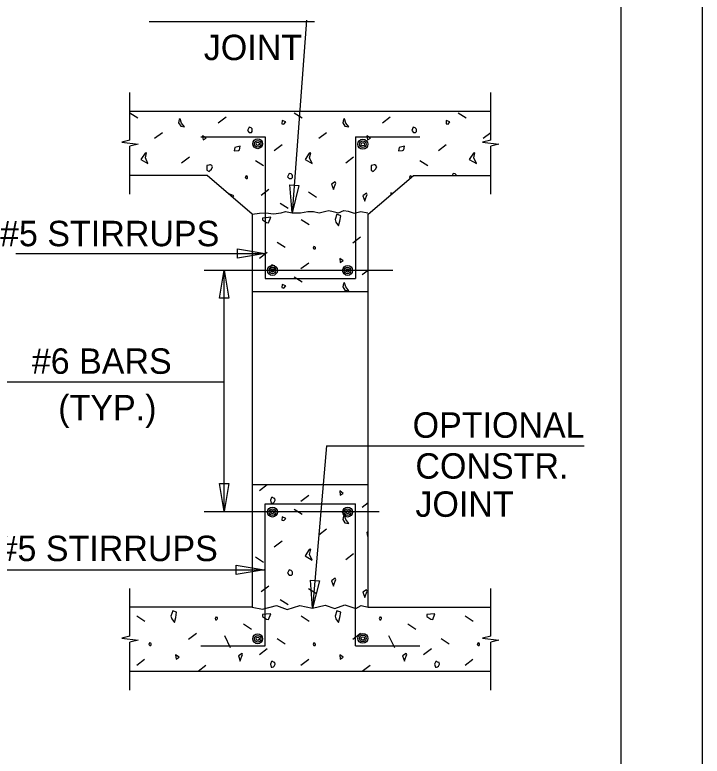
# Model space of a CAD drawing. Extents: x 0 to 34, y 0 to 23.5.
# Drawn here: x 29.778 to 34, y 4.606 to 9.162 of the extents above; entities that cross this region are included whole.
import ezdxf

# ---------------------------------------------------------------- set-up
doc = ezdxf.new("R2010")
doc.units = 0
for name, color, linetype in [('BORDER_ANNO_Cutsheet', 7, 'Continuous'), ('BRDG_ANNO_Anno-Sheet', 7, 'Continuous'), ('BRDG_ANNO_General-Notes', 7, 'Continuous'), ('BRDG_BASE_Dtlctrln', 7, 'Continuous'), ('BRDG_BASE_Obj-Line', 7, 'Continuous'), ('BRDG_BASE_Pattern', 7, 'Continuous'), ('BRDG_BASE_Rebar', 7, 'Continuous')]:
    doc.layers.add(name, color=color, linetype=linetype)

msp = doc.modelspace()

# ---------------------------------------------------------------- linework, layer by layer
at = {"layer": 'BORDER_ANNO_Cutsheet'}
msp.add_lwpolyline([(0, 22), (34, 22), (34, 0), (0, 0)], close=True, dxfattribs=at)
at = {"layer": 'BRDG_ANNO_Anno-Sheet'}
msp.add_lwpolyline([(1.5, 21.5), (33.5, 21.5), (33.5, 0.5), (1.5, 0.5)], close=True, dxfattribs=at)
at = {"layer": 'BRDG_ANNO_General-Notes'}
for p, q in [((30.6025, 9.1206), (31.618, 9.1206)), ((31.5703, 9.1292), (31.4824, 7.9448)), ((31.4667, 8.1175), (31.5235, 8.1133)), ((31.4824, 7.9448), (31.4667, 8.1175)), ((31.5235, 8.1133), (31.4824, 7.9448)), ((31.1453, 7.6665), (31.1453, 7.7235)), ((31.1453, 7.7235), (31.3163, 7.695)), ((29.7843, 7.695), (31.3163, 7.695)), ((31.3163, 7.695), (31.1453, 7.6665)), ((31.0365, 7.4209), (31.0649, 7.5919)), ((31.0649, 6.1102), (31.0649, 7.5919)), ((31.0649, 7.5919), (31.0934, 7.4209)), ((31.0934, 7.4209), (31.0365, 7.4209)), ((29.3401, 6.9065), (31.0649, 6.9065)), ((31.693, 6.5123), (31.6071, 5.5158)), ((31.693, 6.5123), (33.2743, 6.5123)), ((31.0365, 6.2812), (31.0934, 6.2812)), ((31.0649, 6.1102), (31.0365, 6.2812)), ((31.0934, 6.2812), (31.0649, 6.1102)), ((29.728, 5.752), (31.3093, 5.752)), ((31.1383, 5.7235), (31.1383, 5.7805)), ((31.1383, 5.7805), (31.3093, 5.752)), ((31.3093, 5.752), (31.1383, 5.7235)), ((31.5934, 5.6886), (31.6502, 5.6837)), ((31.6071, 5.5158), (31.5934, 5.6886)), ((31.6502, 5.6837), (31.6071, 5.5158))]:
    msp.add_line(p, q, dxfattribs=at)
at = {"layer": 'BRDG_BASE_Dtlctrln'}
for p, q in [((30.9419, 7.5919), (32.1005, 7.5919)), ((30.9419, 6.1102), (32.0158, 6.1102))]:
    msp.add_line(p, q, dxfattribs=at)
at = {"layer": 'BRDG_BASE_Obj-Line'}
for p, q in [((30.485, 8.3912), (30.485, 8.685)), ((32.7017, 8.3912), (32.7017, 8.685)), ((30.485, 8.5704), (32.7017, 8.5704)), ((30.485, 8.3912), (30.435, 8.3788)), ((32.7017, 8.3912), (32.6517, 8.3788)), ((30.435, 8.3788), (30.535, 8.3662)), ((30.535, 8.3662), (30.485, 8.3537)), ((30.485, 8.06), (30.485, 8.3537)), ((32.6517, 8.3788), (32.7517, 8.3662)), ((32.7517, 8.3662), (32.7017, 8.3537)), ((32.7017, 8.06), (32.7017, 8.3537)), ((30.96, 8.1746), (30.485, 8.1746)), ((31.2371, 7.9371), (30.96, 8.1746)), ((31.9496, 7.9371), (32.2267, 8.1746)), ((32.2267, 8.1746), (32.7017, 8.1746)), ((31.2371, 7.9371), (31.2371, 5.5225)), ((31.9496, 5.5225), (31.9496, 7.9371)), ((31.2371, 7.4621), (31.9496, 7.4621)), ((31.2371, 6.2746), (31.9496, 6.2746)), ((30.485, 5.3433), (30.485, 5.6371)), ((32.7017, 5.3433), (32.7017, 5.6371)), ((31.2371, 5.5225), (30.485, 5.5225)), ((31.9496, 5.5225), (32.7017, 5.5225)), ((30.485, 5.3433), (30.435, 5.3308)), ((30.435, 5.3308), (30.535, 5.3183)), ((32.7017, 5.3433), (32.6517, 5.3308)), ((32.6517, 5.3308), (32.7517, 5.3183)), ((30.535, 5.3183), (30.485, 5.3058)), ((30.485, 5.0121), (30.485, 5.3058)), ((32.7517, 5.3183), (32.7017, 5.3058)), ((32.7017, 5.0121), (32.7017, 5.3058)), ((32.7017, 5.1267), (30.485, 5.1267))]:
    msp.add_line(p, q, dxfattribs=at)
for points in [[(31.2371, 7.9371), (31.2813, 7.942), (31.321, 7.9448), (31.3662, 7.9392), (31.4144, 7.9448), (31.4399, 7.9533), (31.4824, 7.9448), (31.5334, 7.9448), (31.5787, 7.9533), (31.6127, 7.9533), (31.6467, 7.9448), (31.6892, 7.9562), (31.7062, 7.9591), (31.7345, 7.9533), (31.7657, 7.9448), (31.7996, 7.9591), (31.8251, 7.9562), (31.8619, 7.942), (31.9044, 7.9533), (31.9469, 7.9448)], [(31.2371, 5.5225), (31.2999, 5.5093), (31.3847, 5.5312), (31.4516, 5.508), (31.5287, 5.5325), (31.6071, 5.5158), (31.6855, 5.5337), (31.7433, 5.5145), (31.8063, 5.5364), (31.8731, 5.5132), (31.9053, 5.5325), (31.9496, 5.5225)]]:
    msp.add_lwpolyline(points, dxfattribs=at)
at = {"layer": 'BRDG_BASE_Pattern'}
for p, q in [((30.485, 8.56), (30.5345, 8.5288)), ((31.0764, 8.5331), (31.0282, 8.4965)), ((31.4934, 8.56), (31.5429, 8.5288)), ((32.0847, 8.5331), (32.0366, 8.4965)), ((32.5018, 8.56), (32.5512, 8.5288)), ((30.6853, 8.4375), (30.6371, 8.4009)), ((31.6936, 8.4375), (31.6455, 8.4009)), ((32.7017, 8.4372), (32.6539, 8.4009)), ((31.4201, 8.3628), (31.372, 8.3262)), ((32.4285, 8.3628), (32.3804, 8.3262)), ((30.8503, 8.2864), (30.8022, 8.2497)), ((31.2571, 8.2667), (31.3066, 8.2355)), ((31.8587, 8.2864), (31.8106, 8.2497)), ((32.2655, 8.2667), (32.315, 8.2355)), ((31.339, 8.0881), (31.2909, 8.0515)), ((31.5815, 8.0731), (31.6309, 8.0421)), ((31.4079, 8.0048), (31.4574, 7.9736)), ((31.5365, 7.9041), (31.5859, 7.8728)), ((31.9021, 7.7954), (31.854, 7.7588)), ((31.3892, 7.7647), (31.4386, 7.7335)), ((31.3287, 7.7016), (31.2806, 7.665)), ((31.5833, 7.6366), (31.5352, 7.6)), ((31.9496, 7.5914), (31.9123, 7.5631)), ((31.4934, 7.5527), (31.5429, 7.5214)), ((31.3287, 6.2726), (31.2806, 6.2359)), ((31.5833, 6.2076), (31.5352, 6.1709)), ((31.9496, 6.1623), (31.9123, 6.134)), ((31.4934, 6.1236), (31.5429, 6.0923)), ((31.6936, 6.0011), (31.6455, 5.9645)), ((31.4201, 5.9264), (31.372, 5.8898)), ((31.8587, 5.8499), (31.8106, 5.8133)), ((31.2571, 5.8303), (31.3066, 5.7991)), ((31.339, 5.6517), (31.2909, 5.6151)), ((31.5815, 5.6367), (31.6309, 5.6057)), ((31.4079, 5.5684), (31.4574, 5.5372)), ((30.5281, 5.4677), (30.5776, 5.4364)), ((31.5365, 5.4677), (31.5859, 5.4364)), ((32.5449, 5.4677), (32.5943, 5.4364)), ((31.1828, 5.4186), (31.2323, 5.3874)), ((32.1912, 5.4186), (32.2407, 5.3874)), ((30.8938, 5.359), (30.8456, 5.3223)), ((31.0653, 5.3479), (31.102, 5.2743)), ((31.9021, 5.359), (31.854, 5.3223)), ((32.0737, 5.3479), (32.1104, 5.2743)), ((31.3892, 5.3283), (31.4386, 5.2971)), ((32.3976, 5.3283), (32.447, 5.2971)), ((31.3287, 5.2652), (31.2806, 5.2286)), ((32.3371, 5.2652), (32.289, 5.2286)), ((30.5749, 5.2002), (30.5268, 5.1636)), ((31.5833, 5.2002), (31.5352, 5.1636)), ((32.5917, 5.2002), (32.5436, 5.1636)), ((30.9521, 5.1633), (30.904, 5.1267)), ((31.9605, 5.1633), (31.9123, 5.1267))]:
    msp.add_line(p, q, dxfattribs=at)
for points in [[(30.7878, 8.5181), (30.7837, 8.4974), (30.7974, 8.4771), (30.8205, 8.4726), (30.8021, 8.4969), (30.7942, 8.5222)], [(31.7961, 8.5181), (31.7921, 8.4974), (31.8058, 8.4771), (31.8289, 8.4726), (31.8105, 8.4969), (31.8026, 8.5222)], [(31.4197, 8.5127), (31.4188, 8.4929), (31.4307, 8.4901), (31.4422, 8.5034)], [(32.4281, 8.5127), (32.4272, 8.4929), (32.4391, 8.4901), (32.4506, 8.5034)], [(31.2167, 8.471), (31.2074, 8.4508), (31.2183, 8.4396), (31.2315, 8.4396), (31.2369, 8.4455), (31.2369, 8.4562), (31.2351, 8.4616), (31.2294, 8.4675)], [(32.2251, 8.471), (32.2158, 8.4508), (32.2267, 8.4396), (32.2399, 8.4396), (32.2453, 8.4455), (32.2453, 8.4562), (32.2435, 8.4616), (32.2378, 8.4675)], [(30.9319, 8.4191), (30.9356, 8.3933), (30.9541, 8.4044)], [(31.9403, 8.4191), (31.944, 8.3933), (31.9625, 8.4044)], [(31.1297, 8.3474), (31.126, 8.3254), (31.1519, 8.3291), (31.1592, 8.3327), (31.1629, 8.3548)], [(32.1381, 8.3474), (32.1344, 8.3254), (32.1603, 8.3291), (32.1676, 8.3327), (32.1713, 8.3548)], [(30.5786, 8.3118), (30.5529, 8.2732), (30.5962, 8.2473), (30.5804, 8.2823), (30.5871, 8.3144)], [(31.587, 8.3118), (31.5613, 8.2732), (31.6046, 8.2473), (31.5888, 8.2823), (31.5955, 8.3144)], [(32.5954, 8.3118), (32.5697, 8.2732), (32.613, 8.2473), (32.5972, 8.2823), (32.6039, 8.3144)], [(30.9585, 8.236), (30.9585, 8.2081), (30.9711, 8.1992), (30.975, 8.2028), (30.9858, 8.2139), (30.9932, 8.2286), (30.9879, 8.236), (30.9805, 8.2396), (30.9769, 8.2396), (30.9696, 8.2376)], [(31.9669, 8.236), (31.9669, 8.2081), (31.9795, 8.1992), (31.9834, 8.2028), (31.9942, 8.2139), (32.0016, 8.2286), (31.9962, 8.236), (31.9889, 8.2396), (31.9853, 8.2396), (31.978, 8.2376)], [(31.1983, 8.1717), (31.1936, 8.1616), (31.1991, 8.1559), (31.2057, 8.1559), (31.2084, 8.1589), (31.2084, 8.1643), (31.2075, 8.1669), (31.2046, 8.1699)], [(31.4628, 8.1873), (31.4535, 8.1671), (31.4643, 8.1558), (31.4776, 8.1558), (31.483, 8.1617), (31.483, 8.1725), (31.4811, 8.1778), (31.4754, 8.1837)], [(31.724, 8.1209), (31.7353, 8.0877), (31.7353, 8.0912), (31.7501, 8.1282), (31.7464, 8.1356)], [(31.9161, 8.0502), (31.9276, 8.017), (31.9276, 8.0205), (31.9422, 8.0576), (31.9385, 8.0649)], [(31.7563, 7.9365), (31.7451, 7.9034), (31.7508, 7.8868), (31.7673, 7.8647), (31.7747, 7.8942), (31.7802, 7.9273)], [(31.3226, 7.9146), (31.3005, 7.9127), (31.3005, 7.9017), (31.3244, 7.8852), (31.3374, 7.8833), (31.3503, 7.9182)], [(31.6148, 7.7386), (31.6102, 7.7285), (31.6156, 7.7229), (31.6222, 7.7229), (31.6249, 7.7258), (31.6249, 7.7313), (31.624, 7.7339), (31.6211, 7.7369)], [(31.7737, 7.6649), (31.7774, 7.6391), (31.7959, 7.6502)], [(31.348, 7.6078), (31.3538, 7.5893), (31.3591, 7.5893), (31.3666, 7.5911), (31.372, 7.5965), (31.3774, 7.6078), (31.3759, 7.6187), (31.3666, 7.6206), (31.3627, 7.6244), (31.3554, 7.6244)], [(31.4197, 7.5053), (31.4188, 7.4855), (31.4307, 7.4828), (31.4422, 7.4961)], [(31.7961, 7.5108), (31.7921, 7.4901), (31.8058, 7.4697), (31.8289, 7.4652), (31.8105, 7.4896), (31.8026, 7.5149)], [(31.7737, 6.2358), (31.7774, 6.21), (31.7959, 6.2211)], [(31.348, 6.1787), (31.3538, 6.1603), (31.3591, 6.1603), (31.3666, 6.1621), (31.372, 6.1674), (31.3774, 6.1787), (31.3759, 6.1896), (31.3666, 6.1916), (31.3627, 6.1954), (31.3554, 6.1954)], [(31.4197, 6.0762), (31.4188, 6.0565), (31.4307, 6.0537), (31.4422, 6.067)], [(31.7961, 6.0817), (31.7921, 6.061), (31.8058, 6.0407), (31.8289, 6.0361), (31.8105, 6.0605), (31.8026, 6.0858)], [(31.587, 5.8754), (31.5613, 5.8368), (31.6046, 5.8109), (31.5888, 5.8459), (31.5955, 5.878)], [(31.4628, 5.7509), (31.4535, 5.7307), (31.4643, 5.7194), (31.4776, 5.7194), (31.483, 5.7253), (31.483, 5.7361), (31.4811, 5.7414), (31.4754, 5.7473)], [(31.724, 5.6845), (31.7353, 5.6513), (31.7353, 5.6548), (31.7501, 5.6918), (31.7464, 5.6992)], [(31.9161, 5.6137), (31.9276, 5.5806), (31.9276, 5.5841), (31.9422, 5.6211), (31.9385, 5.6285)], [(30.7479, 5.5001), (30.7367, 5.467), (30.7424, 5.4504), (30.759, 5.4283), (30.7663, 5.4578), (30.7718, 5.4909)], [(31.3226, 5.4782), (31.3005, 5.4763), (31.3005, 5.4653), (31.3244, 5.4487), (31.3374, 5.4469), (31.3503, 5.4818)], [(31.7563, 5.5001), (31.7451, 5.467), (31.7508, 5.4504), (31.7673, 5.4283), (31.7747, 5.4578), (31.7802, 5.4909)], [(32.3309, 5.4782), (32.3089, 5.4763), (32.3089, 5.4653), (32.3328, 5.4487), (32.3458, 5.4469), (32.3587, 5.4818)], [(31.0083, 5.4529), (31.0113, 5.4436), (31.0139, 5.4436), (31.0177, 5.4446), (31.0204, 5.4472), (31.023, 5.4529), (31.0223, 5.4584), (31.0177, 5.4593), (31.0157, 5.4612), (31.012, 5.4612)], [(32.0167, 5.4529), (32.0196, 5.4436), (32.0223, 5.4436), (32.026, 5.4446), (32.0288, 5.4472), (32.0314, 5.4529), (32.0307, 5.4584), (32.026, 5.4593), (32.0241, 5.4612), (32.0204, 5.4612)], [(30.6064, 5.3022), (30.6018, 5.2921), (30.6072, 5.2865), (30.6138, 5.2865), (30.6165, 5.2894), (30.6165, 5.2948), (30.6156, 5.2975), (30.6128, 5.3005)], [(31.6148, 5.3022), (31.6102, 5.2921), (31.6156, 5.2865), (31.6222, 5.2865), (31.6249, 5.2894), (31.6249, 5.2948), (31.624, 5.2975), (31.6211, 5.3005)], [(32.6232, 5.3022), (32.6185, 5.2921), (32.624, 5.2865), (32.6306, 5.2865), (32.6333, 5.2894), (32.6333, 5.2948), (32.6324, 5.2975), (32.6295, 5.3005)], [(30.7653, 5.2285), (30.769, 5.2027), (30.7875, 5.2138)], [(31.1514, 5.2231), (31.1628, 5.1898), (31.1628, 5.1934), (31.1774, 5.2304), (31.1737, 5.2378)], [(31.7737, 5.2285), (31.7774, 5.2027), (31.7959, 5.2138)], [(32.1597, 5.2231), (32.1711, 5.1898), (32.1711, 5.1934), (32.1858, 5.2304), (32.1821, 5.2378)], [(31.348, 5.1714), (31.3538, 5.1529), (31.3591, 5.1529), (31.3666, 5.1547), (31.372, 5.1601), (31.3774, 5.1714), (31.3759, 5.1823), (31.3666, 5.1842), (31.3627, 5.188), (31.3554, 5.188)], [(32.3564, 5.1714), (32.3622, 5.1529), (32.3675, 5.1529), (32.375, 5.1547), (32.3804, 5.1601), (32.3858, 5.1714), (32.3843, 5.1823), (32.375, 5.1842), (32.3711, 5.188), (32.3637, 5.188)]]:
    msp.add_lwpolyline(points, close=True, dxfattribs=at)
for points in [[(32.2067, 8.1717), (32.202, 8.1616), (32.2063, 8.1571)], [(32.2163, 8.1657), (32.2159, 8.1669), (32.213, 8.1699), (32.2067, 8.1717)], [(32.4711, 8.1873), (32.4653, 8.1746)], [(32.4906, 8.1746), (32.4895, 8.1778), (32.4838, 8.1837), (32.4711, 8.1873)], [(32.0874, 8.0678), (32.0869, 8.0547)], [(32.0973, 8.0637), (32.0874, 8.0678)], [(31.1166, 8.0404), (31.1242, 8.0493), (31.0897, 8.0634)], [(31.9403, 5.9827), (31.944, 5.9569), (31.9496, 5.9602)], [(31.9496, 5.9766), (31.9403, 5.9827)]]:
    msp.add_lwpolyline(points, dxfattribs=at)
at = {"layer": 'BRDG_BASE_Rebar'}
for p, q in [((30.9204, 8.4121), (31.3163, 8.4121)), ((31.3163, 8.4121), (31.3163, 7.5412)), ((31.8704, 8.4121), (31.8704, 7.5412)), ((31.8704, 8.4121), (32.2662, 8.4121)), ((31.3163, 7.5412), (31.8704, 7.5412)), ((31.3163, 5.285), (31.3163, 6.1558)), ((31.3163, 6.1558), (31.8704, 6.1558)), ((31.8704, 5.285), (31.8704, 6.1558)), ((30.9204, 5.285), (31.3163, 5.285)), ((31.8704, 5.285), (32.2662, 5.285))]:
    msp.add_line(p, q, dxfattribs=at)
for centre, radius in [((31.27, 8.3697), 0.0305), ((31.27, 8.3697), 0.0203), ((31.9158, 8.3669), 0.0305), ((31.9158, 8.3669), 0.0203), ((31.27, 8.3697), 0.0102), ((31.9158, 8.3669), 0.0102), ((31.3606, 7.5908), 0.0305), ((31.3606, 7.5908), 0.0203), ((31.8223, 7.5908), 0.0305), ((31.8223, 7.5908), 0.0203), ((31.3606, 7.5908), 0.0102), ((31.8223, 7.5908), 0.0102), ((31.3606, 6.1062), 0.0305), ((31.3606, 6.1062), 0.0203), ((31.3606, 6.1062), 0.0102), ((31.8223, 6.1062), 0.0305), ((31.8223, 6.1062), 0.0203), ((31.8223, 6.1062), 0.0102), ((31.27, 5.3273), 0.0305), ((31.27, 5.3273), 0.0203), ((31.27, 5.3273), 0.0102), ((31.9158, 5.3302), 0.0305), ((31.9158, 5.3302), 0.0203), ((31.9158, 5.3302), 0.0102)]:
    msp.add_circle(centre, radius, dxfattribs=at)

# ---------------------------------------------------------------- texts
at = {"layer": 'BRDG_ANNO_General-Notes'}
for s, p in [('JOINT', (30.939, 8.8834)), ('#5 STIRRUPS', (29.6876, 7.7398)), ('#6 BARS', (29.8826, 6.9558)), ('(TYP.)', (30.045, 6.6698)), ('OPTIONAL', (32.2215, 6.5628)), ('CONSTR.', (32.2387, 6.3114)), ('JOINT', (32.2387, 6.077)), ('#5 STIRRUPS', (29.6783, 5.8047))]:
    msp.add_text(s, height=0.15625, dxfattribs=at).set_placement(p)

doc.saveas('drawing.dxf')
